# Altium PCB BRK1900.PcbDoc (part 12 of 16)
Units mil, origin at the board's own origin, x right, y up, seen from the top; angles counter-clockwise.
Board outline 8858.27 x 5905.51 mil, 10 copper layers (L1-TOP, L2-GND, L3-PWR, L4-GND, L5-PWR, L6-PWR, L7-GND, L8-SIG, L9-GND, L10-BOT), stack 48.824 mil thick; 456 components, 571 nets, 2296 pads, 2416 vias.
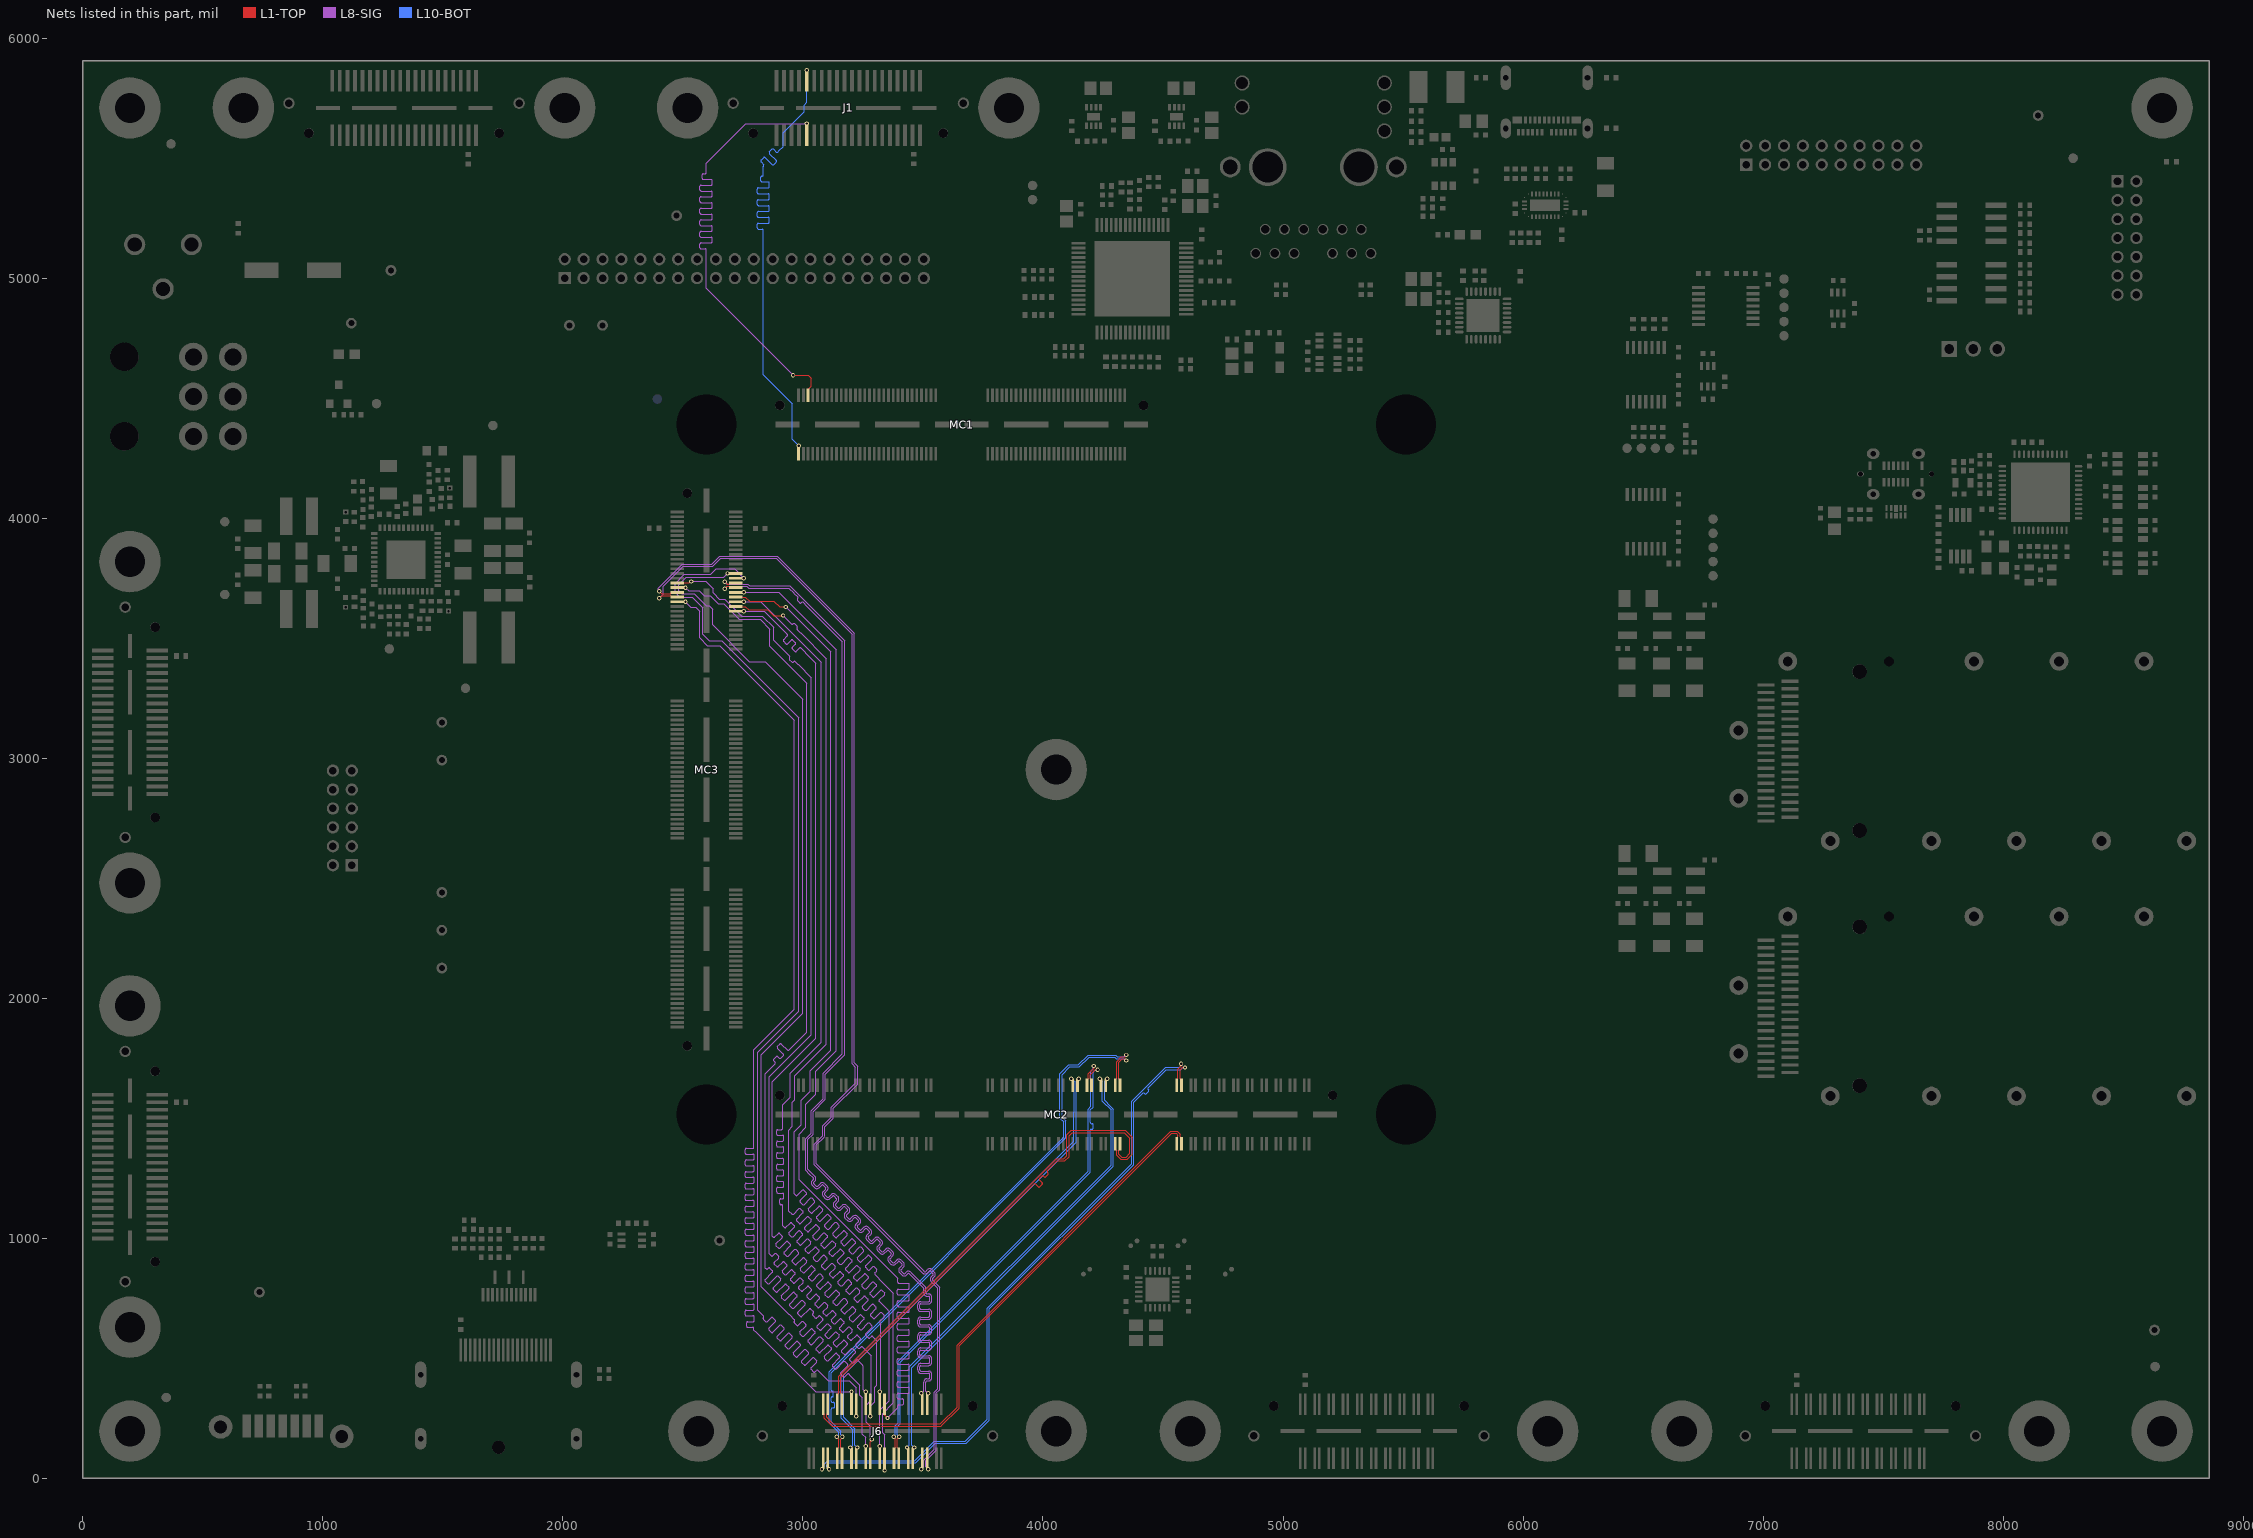
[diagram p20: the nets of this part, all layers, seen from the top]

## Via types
v1: diameter 18, hole 10, L1-TOP to L10-BOT, tented both sides, 2170 vias
v2: diameter 20, hole 10, L1-TOP to L10-BOT, tented both sides, 246 vias

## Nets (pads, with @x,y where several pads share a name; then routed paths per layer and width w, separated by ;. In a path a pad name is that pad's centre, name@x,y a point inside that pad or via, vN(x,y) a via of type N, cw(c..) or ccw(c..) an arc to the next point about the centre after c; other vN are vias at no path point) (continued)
SZG_PORTD_S26: J1.31 MC1.2 | length 2214
  L10-BOT w4.55: 2830.04,5424.99 ccw(c2830.04,5420.08) 2825.13,5420.08 2825.13,5405.35 ccw(c2830.04,5405.35) 2830.04,5400.44 2855.09,5400.44 cw(c2855.09,5395.53) 2860,5395.53 2860,5380.8 cw(c2855.09,5380.8) 2855.09,5375.89 2814.91,5375.89 ccw(c2814.91,5370.98) 2810,5370.98 2810,5356.25 ccw(c2814.91,5356.25) 2814.91,5351.34 2855.09,5351.34 cw(c2855.09,5346.43) 2860,5346.43 2860,5331.7 cw(c2855.09,5331.7) 2855.09,5326.79 2814.91,5326.79 ccw(c2814.91,5321.88) 2810,5321.88 2810,5307.15 ccw(c2814.91,5307.15) 2814.91,5302.24 2855.09,5302.24 cw(c2855.09,5297.33) 2860,5297.33 2860,5282.6 cw(c2855.09,5282.6) 2855.09,5277.69 2814.91,5277.69 ccw(c2814.91,5272.78) 2810,5272.78 2810,5258.05 ccw(c2814.91,5258.05) 2814.91,5253.14 2855.09,5253.14 cw(c2855.09,5248.23) 2860,5248.23 2860,5233.5 cw(c2855.09,5233.5) 2855.09,5228.59 2814.91,5228.59 ccw(c2814.91,5223.68) 2810,5223.68 2810,5208.95 ccw(c2814.91,5208.95) 2814.91,5204.04 2830.09,5204.04 cw(c2830.09,5199.13) 2835,5199.13 2835,5196.85 2835,4597 2956,4476 2956,4328.39 v1(2982.28,4302.11) ; 2830.09,5424.99 ccw(c2830.09,5429.9) 2835,5429.9 2835,5448.82 2835,5464.21 2835,5464.92 2836.25,5466.18 ccw(c2832.78,5469.65) 2836.25,5473.12 2825.52,5483.85 cw(c2828.99,5487.33) 2825.52,5490.8 2835.94,5501.21 cw(c2839.41,5497.74) 2842.88,5501.21 2871.29,5472.8 ccw(c2874.76,5476.27) 2878.24,5472.8 2888.65,5483.22 ccw(c2885.18,5486.69) 2888.65,5490.16 2860.24,5518.57 cw(c2863.71,5522.04) 2860.24,5525.52 2870.66,5535.93 cw(c2874.13,5532.46) 2877.6,5535.93 2888.33,5525.2 ccw(c2891.8,5528.67) 2895.28,5525.2 2901.57,5531.5 2917.32,5547.24 2917.32,5606.3 3004.63,5693.61 3004.63,5720.36 3015.78,5731.51 v1@3015.78,5869.46
  other v1: 3015.79,5866.17
SZG_PORTD_S27: J1.32 MC1.5 | length 2265.5
  L1-TOP w4.55: v1(2959,4595) 3022.86,4595 3034.34,4583.52 3034.34,4549.34 3021.65,4536.65 MC1.5@3021.65,4511.42
  L8-SIG w4.05: v1(2959,4595) 2597,4957 2597,5115.41 2597,5117.44 ccw(c2592.19,5117.44) 2592.19,5122.25 2575.88,5122.25 cw(c2575.88,5127.06) 2571.07,5127.06 2571.07,5141.49 cw(c2575.88,5141.49) 2575.88,5146.3 2617.19,5146.3 ccw(c2617.19,5151.11) 2622,5151.11 2622,5165.54 ccw(c2617.19,5165.54) 2617.19,5170.35 2575.88,5170.35 cw(c2575.88,5175.16) 2571.07,5175.16 2571.07,5189.59 cw(c2575.88,5189.59) 2575.88,5194.4 2617.19,5194.4 ccw(c2617.19,5199.21) 2622,5199.21 2622,5213.64 ccw(c2617.19,5213.64) 2617.19,5218.45 2575.88,5218.45 cw(c2575.88,5223.26) 2571.07,5223.26 2571.07,5237.69 cw(c2575.88,5237.69) 2575.88,5242.5 2617.19,5242.5 ccw(c2617.19,5247.31) 2622,5247.31 2622,5261.74 ccw(c2617.19,5261.74) 2617.19,5266.55 2575.88,5266.55 cw(c2575.88,5271.36) 2571.07,5271.36 2571.07,5285.79 cw(c2575.88,5285.79) 2575.88,5290.6 2617.19,5290.6 ccw(c2617.19,5295.41) 2622,5295.41 2622,5309.84 ccw(c2617.19,5309.84) 2617.19,5314.65 2575.88,5314.65 cw(c2575.88,5319.46) 2571.07,5319.46 2571.07,5333.89 cw(c2575.88,5333.89) 2575.88,5338.7 2617.19,5338.7 ccw(c2617.19,5343.51) 2622,5343.51 2622,5357.94 ccw(c2617.19,5357.94) 2617.19,5362.75 2575.88,5362.75 cw(c2575.88,5367.56) 2571.07,5367.56 2571.07,5381.99 cw(c2575.88,5381.99) 2575.88,5386.8 2617.19,5386.8 ccw(c2617.19,5391.61) 2622,5391.61 2622,5406.04 ccw(c2617.19,5406.04) 2617.19,5410.85 2584.93,5410.85 cw(c2584.93,5415.66) 2580.12,5415.66 2580.12,5430.09 cw(c2584.93,5430.09) 2584.93,5434.9 2592.19,5434.9 ccw(c2592.19,5439.71) 2597,5439.71 2597,5464.57 2597,5478.89 2761.97,5643.86 v1(3015.78,5643.86)
SZG_PORTE_C2P_CLKN: J6.36 MC3.150 | length 4941.1
  L1-TOP w3.3: v1@2675.08,3734.25 2676.08,3734.25 2685.36,3724.97 2692.1,3724.97 2697.44,3730.32 MC3.150@2720.08,3730.32
  L8-SIG w3.15: v1@2675.08,3734.25 2684.36,3724.97 2770.76,3724.97 2777.99,3717.74 2944.99,3717.74 3173.87,3488.86 3173.87,1764.49 3093.64,1684.26 3093.64,1578.64 3043,1528 3043,1434.07 3020.95,1412.02 3020.95,1287.05 3031.65,1276.36 3049.97,1258.04 cw(c3040.33,1248.4) 3049.97,1238.76 3045.22,1234.01 ccw(c3048.49,1230.74) 3045.22,1227.46 3055.04,1217.64 ccw(c3058.31,1220.92) 3061.58,1217.64 3071.63,1227.69 cw(c3081.27,1218.05) 3090.91,1227.69 3100.73,1217.87 cw(c3091.09,1208.23) 3102.05,1200.12 3102.05,1199.91 3090.67,1188.53 ccw(c3093.94,1185.26) 3090.67,1181.98 3100.49,1172.16 ccw(c3103.76,1175.43) 3107.04,1172.16 ; 3107.06,1172.18 3117.1,1182.22 cw(c3126.74,1172.58) 3136.37,1182.22 3146.19,1172.4 cw(c3136.56,1162.76) 3147.51,1154.65 3147.51,1154.44 3136.13,1143.06 ccw(c3139.41,1139.79) 3136.13,1136.51 3145.96,1126.69 ccw(c3149.23,1129.97) 3152.5,1126.69 3162.56,1136.75 cw(c3172.2,1127.12) 3181.84,1136.75 3191.66,1126.93 cw(c3182.02,1117.29) 3192.98,1109.19 3192.98,1108.97 3181.6,1097.6 ccw(c3184.87,1094.32) 3181.6,1091.05 3191.42,1081.23 ccw(c3194.7,1084.5) 3197.97,1081.23 ; 3197.99,1081.25 3208.03,1091.29 cw(c3217.67,1081.65) 3227.31,1091.29 3237.13,1081.46 cw(c3227.49,1071.83) 3238.45,1063.72 3238.45,1063.51 3227.07,1052.13 ccw(c3230.34,1048.85) 3227.07,1045.58 3236.89,1035.76 ccw(c3240.16,1039.03) 3243.44,1035.76 ; 3243.46,1035.78 3253.5,1045.82 cw(c3263.14,1036.18) 3272.77,1045.82 3282.6,1036 cw(c3272.96,1026.36) 3283.91,1018.25 3283.91,1018.04 3272.53,1006.66 ccw(c3275.81,1003.39) 3272.53,1000.11 3282.36,990.29 ccw(c3285.63,993.57) 3288.9,990.29 3298.96,1000.35 cw(c3308.6,990.72) 3318.24,1000.35 3328.06,990.53 cw(c3318.42,980.89) 3329.38,972.79 3329.38,972.57 3318,961.2 ccw(c3321.27,957.92) 3318,954.65 3327.82,944.83 ccw(c3331.1,948.1) 3334.37,944.83 ; 3334.39,944.85 3344.43,954.89 cw(c3354.07,945.25) 3363.71,954.89 3373.53,945.06 cw(c3363.89,935.43) 3374.85,927.32 3374.85,927.11 3363.47,915.73 ccw(c3366.74,912.45) 3363.47,909.18 3373.29,899.36 ccw(c3376.56,902.63) 3379.84,899.36 ; 3379.86,899.38 3389.9,909.42 cw(c3399.54,899.78) 3409.17,909.42 3419,899.6 cw(c3409.36,889.96) 3420.31,881.85 3420.31,881.64 3408.93,870.26 ccw(c3412.21,866.99) 3408.93,863.71 3418.76,853.89 ccw(c3422.03,857.17) 3425.3,853.89 ; 3425.33,853.91 3430.07,858.66 cw(c3439.71,849.02) 3449.35,858.66 3453.64,854.36 3511.93,796.07 3511.93,779.4 3511.93,773.33 ccw(c3516.56,773.33) 3516.56,768.7 3523.3,768.7 cw(c3523.3,755.07) 3536.93,755.07 3536.93,741.17 cw(c3523.3,741.17) 3523.3,727.54 3491.56,727.54 ccw(c3491.56,722.91) 3486.93,722.91 3486.93,709.03 ccw(c3491.56,709.03) 3491.56,704.39 3523.3,704.39 cw(c3523.3,690.76) 3536.93,690.76 3536.93,676.87 cw(c3523.3,676.87) 3523.3,663.24 3491.56,663.25 ccw(c3491.56,658.62) 3486.93,658.62 3486.93,644.72 ccw(c3491.56,644.72) 3491.56,640.09 3523.3,640.09 cw(c3523.3,626.46) 3536.93,626.46 3536.93,612.58 cw(c3523.3,612.58) 3523.3,598.95 3491.56,598.95 ccw(c3491.56,594.32) 3486.93,594.32 3486.93,580.42 ccw(c3491.56,580.42) 3491.56,575.79 3523.3,575.79 cw(c3523.3,562.16) 3536.93,562.16 3536.93,548.28 cw(c3523.3,548.28) 3523.3,534.64 3491.56,534.64 ccw(c3491.56,530.01) 3486.93,530.01 3486.93,516.12 ccw(c3491.56,516.12) 3491.56,511.49 3523.3,511.5 cw(c3523.3,497.87) 3536.93,497.87 3536.93,483.97 cw(c3523.3,483.97) 3523.3,470.34 3491.56,470.34 ccw(c3491.56,465.71) 3486.93,465.71 3486.93,451.83 ccw(c3491.56,451.83) 3491.56,447.2 3523.3,447.2 cw(c3523.3,433.57) 3536.93,433.57 3536.93,419.67 cw(c3523.3,419.67) 3523.3,406.04 3516.56,406.04 ccw(c3516.56,401.41) 3511.93,401.41 3511.93,374.02 3511.93,364.12 v1@3521.21,354.84
  other v1: 3522.31,354.84 2675.08,3735.25
SZG_PORTE_C2P_CLKP: J6.34 MC3.148 | length 4941
  L1-TOP w3.3: v1@2675.08,3706.69 2676.18,3706.69 2685.46,3715.97 2692.1,3715.97 2697.44,3710.63 MC3.148@2720.08,3710.63
  L8-SIG w3.15: v1@2675.08,3706.69 2684.36,3715.97 2767.03,3715.97 2774.26,3708.74 2941.26,3708.74 2960.83,3689.17 2961.94,3688.06 2978.31,3671.69 cw(c2975.04,3668.42) 2978.31,3665.14 2976.83,3663.66 ccw(c2980.1,3660.38) 2976.83,3657.11 2986.65,3647.29 ccw(c2989.92,3650.56) 2993.2,3647.29 2994.68,3648.77 cw(c2997.95,3645.5) 3001.23,3648.77 3014.83,3635.17 3015.95,3634.05 3164.87,3485.13 3164.87,1768.22 3084.64,1687.99 3084.64,1582.36 3034,1531.73 3034,1437.79 3011.95,1415.74 3011.95,1283.33 3025.28,1269.99 3043.6,1251.67 cw(c3040.33,1248.4) 3043.6,1245.13 3038.85,1240.38 ccw(c3048.49,1230.74) 3038.88,1221.07 3048.64,1211.31 ccw(c3058.31,1220.92) 3067.95,1211.28 3077.99,1221.32 cw(c3081.27,1218.05) 3084.54,1221.32 3094.36,1211.5 cw(c3091.09,1208.23) 3094.36,1204.95 3084.3,1194.89 ccw(c3093.94,1185.26) 3084.33,1175.59 3094.1,1165.82 ccw(c3103.76,1175.43) 3111.87,1164.48 3112.08,1164.48 3123.46,1175.86 cw(c3126.74,1172.58) 3130.01,1175.86 3139.83,1166.03 cw(c3136.56,1162.76) 3139.83,1159.49 ; 3139.81,1159.46 3129.77,1149.43 ccw(c3139.41,1139.79) 3129.8,1130.12 3139.56,1120.36 ccw(c3149.23,1129.97) 3157.34,1119.01 3157.55,1119.01 3168.93,1130.39 cw(c3172.2,1127.12) 3175.48,1130.39 3185.3,1120.57 cw(c3182.02,1117.29) 3185.3,1114.02 ; 3185.27,1114 3175.24,1103.96 ccw(c3184.87,1094.32) 3175.27,1084.66 3185.03,1074.89 ccw(c3194.7,1084.5) 3202.8,1073.54 3203.02,1073.54 3214.39,1084.92 cw(c3217.67,1081.65) 3220.94,1084.92 3230.76,1075.1 cw(c3227.49,1071.83) 3230.76,1068.55 3220.7,1058.49 ccw(c3230.34,1048.85) 3220.73,1039.19 3230.5,1029.42 ccw(c3240.16,1039.03) 3248.27,1028.08 3248.48,1028.08 3259.86,1039.46 cw(c3263.14,1036.18) 3266.41,1039.46 3276.23,1029.63 cw(c3272.96,1026.36) 3276.23,1023.09 ; 3276.21,1023.06 3266.17,1013.03 ccw(c3275.81,1003.39) 3266.2,993.72 3275.96,983.96 ccw(c3285.63,993.57) 3293.74,982.61 3293.95,982.61 3305.33,993.99 cw(c3308.6,990.72) 3311.88,993.99 3321.7,984.17 cw(c3318.42,980.89) 3321.7,977.62 ; 3321.68,977.6 3311.64,967.56 ccw(c3321.27,957.92) 3311.67,948.25 3321.43,938.49 ccw(c3331.1,948.1) 3339.2,937.14 3339.42,937.14 3350.8,948.52 cw(c3354.07,945.25) 3357.34,948.52 3367.16,938.7 cw(c3363.89,935.43) 3367.16,932.15 3357.1,922.09 ccw(c3366.74,912.45) 3357.13,902.79 3366.9,893.02 ccw(c3376.56,902.63) 3384.67,891.68 3384.88,891.68 3396.26,903.06 cw(c3399.54,899.78) 3402.81,903.06 3412.63,893.23 cw(c3409.36,889.96) 3412.63,886.69 ; 3412.61,886.66 3402.57,876.63 ccw(c3412.21,866.99) 3402.6,857.32 3412.36,847.56 ccw(c3422.03,857.17) 3430.14,846.21 3430.35,846.21 3436.43,852.29 cw(c3439.71,849.02) 3442.98,852.29 3447.28,848 3502.93,792.35 3502.93,779.4 3502.93,773.33 ccw(c3516.56,773.33) 3516.56,759.7 3523.3,759.7 cw(c3523.3,755.07) 3527.93,755.07 3527.93,741.17 cw(c3523.3,741.17) 3523.3,736.54 3491.56,736.54 ccw(c3491.56,722.91) 3477.93,722.91 3477.93,709.03 ccw(c3491.56,709.03) 3491.56,695.39 3523.3,695.39 cw(c3523.3,690.76) 3527.93,690.76 3527.93,676.87 cw(c3523.3,676.87) 3523.3,672.24 3491.56,672.25 ccw(c3491.56,658.62) 3477.93,658.62 3477.93,644.72 ccw(c3491.56,644.72) 3491.56,631.09 3523.3,631.09 cw(c3523.3,626.46) 3527.93,626.46 3527.93,612.58 cw(c3523.3,612.58) 3523.3,607.95 3491.56,607.95 ccw(c3491.56,594.32) 3477.93,594.32 3477.93,580.42 ccw(c3491.56,580.42) 3491.56,566.79 3523.3,566.79 cw(c3523.3,562.16) 3527.93,562.16 3527.93,548.28 cw(c3523.3,548.28) 3523.3,543.64 3491.56,543.64 ccw(c3491.56,530.01) 3477.93,530.01 3477.93,516.12 ccw(c3491.56,516.12) 3491.56,502.49 3523.3,502.5 cw(c3523.3,497.87) 3527.93,497.87 3527.93,483.97 cw(c3523.3,483.97) 3523.3,479.34 3491.56,479.34 ccw(c3491.56,465.71) 3477.93,465.71 3477.93,451.83 ccw(c3491.56,451.83) 3491.56,438.2 3523.3,438.2 cw(c3523.3,433.57) 3527.93,433.57 3527.93,419.67 cw(c3523.3,419.67) 3523.3,415.04 3516.56,415.04 ccw(c3516.56,401.41) 3502.93,401.41 3502.93,374.02 3502.93,364.12 v1@3493.65,354.84
  other v1: 3492.55,354.84 2675.08,3705.59
SZG_PORTE_P2C_CLKN: J6.35 MC3.145 | length 4940.7
  L1-TOP w3.3: v1@2401.77,3694.88 2411.05,3685.6 2448.88,3685.6 2454.22,3690.95 MC3.145@2476.77,3690.95
  L8-SIG w3.15: v1(2401.77,3695.88) 2401.77,3699.9 2397.91,3703.76 2397.91,3708.63 2497.21,3807.94 2619.94,3807.94 2654,3842 2892.73,3842 3213.72,3521 3213.72,1731.59 3227.84,1717.47 3227.84,1642.84 3127,1542 3127,1500.1 3091.64,1464.73 3091.64,1424.64 3089,1422 3056.24,1389.24 3056.24,1310.82 3500.82,866.24 3505.11,861.94 ccw(c3508.39,865.22) 3511.66,861.94 3518.95,869.23 cw(c3528.59,859.59) 3538.22,869.23 3548.05,859.41 cw(c3538.41,849.77) 3548.05,840.13 3540.76,832.85 ccw(c3544.03,829.57) 3540.76,826.3 3563.45,803.61 3570,797.06 3570,369.93 3556,355.93 3556,117.07 3511.93,73 3511.93,48.14 v1@3521.21,38.86
  other v1: 3522.31,38.86
SZG_PORTE_P2C_CLKP: J6.33 MC3.143 | length 4939.9
  L1-TOP w3.3: v1@2401.77,3667.32 2411.05,3676.6 2448.69,3676.6 2454.03,3671.26 MC3.143@2476.77,3671.26
  L8-SIG w3.15: v1@2401.77,3667.32 2417.46,3683.01 2417.46,3715.46 2500.94,3798.94 2623.67,3798.94 2657.73,3833 2889,3833 3204.72,3517.28 3204.72,1727.86 3218.84,1713.74 3218.84,1646.57 3118,1545.73 3118,1503.83 3082.64,1468.46 3082.64,1428.36 3047.24,1392.97 3047.24,1307.09 3494.45,859.88 3498.72,855.61 ccw(c3508.39,865.22) 3518.03,855.58 3525.31,862.87 cw(c3528.59,859.59) 3531.86,862.87 3541.68,853.05 cw(c3538.41,849.77) 3541.68,846.5 3534.4,839.21 ccw(c3544.03,829.57) 3534.42,819.91 3557.09,797.24 3561,793.33 3561,373.66 3547,359.66 3547,120.8 3502.93,76.73 3502.93,48.14 v1@3493.65,38.86
  other v1: 3492.55,38.86 2401.77,3666.22
SZG_PORTE_REFCLKN: J6.15 MC2.67 | length 1966.5
  L10-BOT w3.3: v1(3227.03,128.86) 3216.65,139.24 3216.65,206.46 3169.29,253.82 3169.29,432.15 4137.89,1400.76 4137.89,1522.23 4138.36,1522.7 4138.36,1654.15 v1(4149.61,1665.4)
SZG_PORTE_REFCLKP: J6.13 MC2.65 | length 1966.5
  L10-BOT w3.3: v1(3197.28,128.86) 3207.65,139.24 3207.65,202.73 3160.29,250.09 3160.29,435.88 4128.89,1404.48 4128.89,1525.96 4129.36,1526.42 4129.36,1654.15 v1(4118.11,1665.4)
SZG_PORTE_RX0N: J6.7 MC2.83 | length 2732.1
  L1-TOP w3.3: MC2.83@4576.77,1637.4 4576.77,1660.04 4571.43,1665.38 4571.43,1701.35 4585.25,1715.17 4588.83,1711.59 v1(4591.56,1711.59)
  L10-BOT w3.3: v1(3108.92,38.86) 3098.54,49.24 3098.54,55.12 3107.91,64.48 3469.22,64.48 3550.74,146 3680.73,146 3774.08,239.35 3776.72,241.99 3776.72,705.85 4377.95,1307.09 4377.95,1566.93 4397.51,1586.48 4415.15,1604.12 cw(c4418.44,1600.83) 4421.74,1604.12 4423.25,1602.61 ccw(c4426.54,1605.91) 4429.84,1602.61 4439.72,1612.5 ccw(c4436.43,1615.79) 4439.72,1619.09 4438.21,1620.6 cw(c4441.51,1623.89) 4438.21,1627.19 4454.19,1643.16 4514.25,1703.23 4573.31,1703.23 4580.05,1709.97 4589.95,1709.97 v1(4591.56,1711.59)
SZG_PORTE_RX0P: J6.5 MC2.81 | length 2732.1
  L1-TOP w3.3: MC2.81@4557.09,1637.4 4557.09,1660.04 4562.43,1665.38 4562.43,1705.08 4578.88,1721.53 4575.3,1725.12 v1(4575.3,1727.85)
  L10-BOT w3.3: v1(3079.17,38.86) 3089.54,49.24 3089.54,58.85 3104.18,73.48 3465.49,73.48 3547.01,155 3677,155 3767.72,245.72 3767.72,709.58 4368.95,1310.81 4368.95,1570.66 4510.53,1712.23 4569.58,1712.23 4573.69,1716.34 4573.69,1726.24 v1(4575.3,1727.85)
SZG_PORTE_RX1N: J6.11 MC2.79 | length 2505.9
  L1-TOP w3.3: J6.11@3162.94,83.86 3162.94,123.03 3157.6,128.37 3157.6,163.95 3164.6,170.95 v1(3164.6,173.23) ; MC2.79@4320.87,1637.4 4320.87,1660.04 4315.52,1665.38 4315.52,1732.85 4330.71,1748.03 4342.52,1748.03 4346.46,1744.09 v1(4346.46,1741.03)
  L10-BOT w3.3: v1(3164.6,173.23) 3164.6,175.51 3157.6,182.51 3157.6,196.27 3118.11,235.76 3118.11,263.78 3118.11,288.73 cw(c3122.77,288.73) 3122.77,293.39 3127.04,293.39 ccw(c3127.04,298.05) 3131.7,298.05 3131.7,312.03 ccw(c3127.04,312.03) 3127.04,316.69 3122.77,316.69 cw(c3122.77,321.35) 3118.11,321.35 3118.11,335.33 cw(c3122.77,335.33) 3122.77,339.99 ccw(c3122.77,344.65) 3127.43,344.65 3127.43,358.63 ccw(c3122.77,358.63) 3122.77,363.29 cw(c3122.77,367.95) 3118.11,367.95 3118.11,401.57 3118.11,440.94 4095.61,1418.45 4095.61,1489.26 4079.83,1505.05 4079.83,1682.19 4111.64,1714.01 4151.01,1714.01 4191.79,1754.78 4298.58,1754.78 4305.33,1748.03 4337.17,1748.03 4344.17,1741.03 v1(4346.46,1741.03)
SZG_PORTE_RX1P: J6.9 MC2.77 | length 2505.9
  L1-TOP w3.3: v1(3141.6,173.23) 3141.6,170.95 3148.6,163.95 3148.6,128.37 3143.26,123.03 J6.9@3143.26,83.86 ; MC2.77@4301.18,1637.4 4301.18,1660.04 4306.52,1665.38 4306.52,1736.57 4326.98,1757.03 4342.52,1757.03 4346.46,1760.97 v1(4346.46,1764.03)
  L10-BOT w3.3: v1(3141.6,173.23) 3141.6,175.51 3148.6,182.51 3148.6,192.54 3109.11,232.03 3109.11,401.57 3109.11,444.67 4086.61,1422.18 4086.61,1485.53 4070.83,1501.32 4070.83,1685.92 4107.92,1723.01 4147.29,1723.01 4188.06,1763.78 4302.31,1763.78 4309.06,1757.03 4337.17,1757.03 4344.17,1764.03 v1(4346.46,1764.03)
SZG_PORTE_RX2N: J6.31 MC2.75 | length 1908.2
  L10-BOT w3.3: v1(3463.26,128.86) 3452.88,139.24 3452.88,460.75 4292.46,1300.34 4292.46,1538.54 4278.02,1552.98 4256.47,1574.53 4256.47,1654.15 v1(4267.72,1665.4)
SZG_PORTE_RX2P: J6.29 MC2.73 | length 1908.2
  L10-BOT w3.3: v1(3433.5,128.86) 3443.88,139.24 3443.88,464.48 4283.46,1304.07 4283.46,1534.81 4247.47,1570.8 4247.47,1654.15 v1(4236.22,1665.4)
SZG_PORTE_RX3N: J6.27 MC2.71 | length 2079.1
  L1-TOP w3.3: J6.27@3399.16,83.86 3399.16,123.03 3393.82,128.37 3393.82,165.17 3400.82,172.17 v1(3400.82,173.23) ; MC2.71@4202.76,1637.4 4202.76,1660.04 4197.41,1665.38 4197.41,1681.67 4220.47,1704.72 4223.45,1701.74 v1(4227.39,1701.74)
  L10-BOT w3.3: v1(3400.82,173.23) 3400.82,175.51 3393.82,182.51 3393.82,185.96 3393.82,215.2 3406,227.39 3406,484.63 4197.41,1276.04 4197.41,1425.2 4197.41,1450.15 cw(c4202.07,1450.15) 4202.07,1454.81 4204.21,1454.81 ccw(c4204.21,1459.47) 4208.87,1459.47 4208.87,1473.45 ccw(c4204.21,1473.45) 4204.21,1478.11 4202.07,1478.11 cw(c4202.07,1482.77) 4197.41,1482.77 4197.41,1500 4197.41,1535.08 4208.66,1546.33 4208.66,1692.91 4215.88,1700.13 4225.78,1700.13 v1(4227.39,1701.74)
SZG_PORTE_RX3P: J6.25 MC2.69 | length 2079.1
  L1-TOP w3.3: v1(3377.82,173.23) 3377.82,172.17 3384.82,165.17 3384.82,128.37 3379.48,123.03 J6.25@3379.48,83.86 ; MC2.69@4183.07,1637.4 4183.07,1660.04 4188.41,1665.38 4188.41,1685.39 4214.11,1711.09 4211.13,1714.07 v1(4211.13,1718.01)
  L10-BOT w3.3: v1(3377.82,173.23) 3377.82,175.51 3384.82,182.51 3384.82,189.68 3384.82,218.93 3397,231.12 3397,488.35 4188.41,1279.76 4188.41,1538.81 4199.66,1550.05 4199.66,1696.64 4209.51,1706.49 4209.51,1716.39 v1(4211.13,1718.01)
SZG_PORTE_S0: J6.14 MC3.141 | length 4899.6
  L8-SIG w4.05: v1(2510.77,3651.58) 2533.46,3628.88 2552.83,3628.88 2569.47,3612.25 2569.47,3501.4 2602.36,3468.5 2653.5,3468.5 2964.38,3157.62 2964.38,1954.01 2796,1785.62 2796,1405.51 2796,1379.44 cw(c2791.19,1379.44) 2791.19,1374.63 2764.15,1374.63 ccw(c2764.15,1369.82) 2759.34,1369.82 2759.34,1355.39 ccw(c2764.15,1355.39) 2764.15,1350.58 2792.04,1350.58 cw(c2792.04,1345.77) 2796.85,1345.77 2796.85,1331.34 cw(c2792.04,1331.34) 2792.04,1326.53 2764.15,1326.53 ccw(c2764.15,1321.72) 2759.34,1321.72 2759.34,1307.29 ccw(c2764.15,1307.29) 2764.15,1302.48 2792.04,1302.48 cw(c2792.04,1297.67) 2796.85,1297.67 2796.85,1283.24 cw(c2792.04,1283.24) 2792.04,1278.43 2764.15,1278.43 ccw(c2764.15,1273.62) 2759.34,1273.62 2759.34,1259.19 ccw(c2764.15,1259.19) 2764.15,1254.38 2792.04,1254.38 cw(c2792.04,1249.57) 2796.85,1249.57 2796.85,1235.14 cw(c2792.04,1235.14) 2792.04,1230.33 2764.15,1230.33 ccw(c2764.15,1225.52) 2759.34,1225.52 2759.34,1211.09 ccw(c2764.15,1211.09) 2764.15,1206.28 2792.04,1206.28 cw(c2792.04,1201.47) 2796.85,1201.47 2796.85,1187.04 cw(c2792.04,1187.04) 2792.04,1182.23 2764.15,1182.23 ccw(c2764.15,1177.42) 2759.34,1177.42 2759.34,1162.99 ccw(c2764.15,1162.99) 2764.15,1158.18 2792.04,1158.18 cw(c2792.04,1153.37) 2796.85,1153.37 2796.85,1138.94 cw(c2792.04,1138.94) 2792.04,1134.13 2764.15,1134.13 ccw(c2764.15,1129.32) 2759.34,1129.32 2759.34,1114.89 ccw(c2764.15,1114.89) 2764.15,1110.08 2792.04,1110.08 cw(c2792.04,1105.27) 2796.85,1105.27 2796.85,1090.84 cw(c2792.04,1090.84) 2792.04,1086.03 2764.15,1086.03 ccw(c2764.15,1081.22) 2759.34,1081.22 2759.34,1066.79 ccw(c2764.15,1066.79) 2764.15,1061.98 2792.04,1061.98 cw(c2792.04,1057.17) 2796.85,1057.17 2796.85,1042.74 cw(c2792.04,1042.74) 2792.04,1037.93 2764.15,1037.93 ccw(c2764.15,1033.12) 2759.34,1033.12 2759.34,1018.69 ccw(c2764.15,1018.69) 2764.15,1013.88 2792.04,1013.88 cw(c2792.04,1009.07) 2796.85,1009.07 2796.85,994.64 cw(c2792.04,994.64) 2792.04,989.83 2764.15,989.83 ccw(c2764.15,985.02) 2759.34,985.02 2759.34,970.59 ccw(c2764.15,970.59) 2764.15,965.78 2792.04,965.78 cw(c2792.04,960.97) 2796.85,960.97 2796.85,946.54 cw(c2792.04,946.54) 2792.04,941.73 2764.15,941.73 ccw(c2764.15,936.92) 2759.34,936.92 2759.34,922.49 ccw(c2764.15,922.49) 2764.15,917.68 2792.04,917.68 cw(c2792.04,912.87) 2796.85,912.87 2796.85,898.44 cw(c2792.04,898.44) 2792.04,893.63 2764.15,893.63 ccw(c2764.15,888.82) 2759.34,888.82 2759.34,874.39 ccw(c2764.15,874.39) 2764.15,869.58 2792.04,869.58 cw(c2792.04,864.77) 2796.85,864.77 2796.85,850.34 cw(c2792.04,850.34) 2792.04,845.53 2764.15,845.53 ccw(c2764.15,840.72) 2759.34,840.72 2759.34,826.29 ccw(c2764.15,826.29) 2764.15,821.48 2792.04,821.48 cw(c2792.04,816.67) 2796.85,816.67 2796.85,802.24 cw(c2792.04,802.24) 2792.04,797.43 2764.15,797.43 ccw(c2764.15,792.62) 2759.34,792.62 2759.34,778.19 ccw(c2764.15,778.19) 2764.15,773.38 2792.04,773.38 cw(c2792.04,768.57) 2796.85,768.57 2796.85,754.14 cw(c2792.04,754.14) 2792.04,749.33 2764.15,749.33 ccw(c2764.15,744.52) 2759.34,744.52 2759.34,730.09 ccw(c2764.15,730.09) 2764.15,725.28 2792.04,725.28 cw(c2792.04,720.47) 2796.85,720.47 2796.85,706.04 cw(c2792.04,706.04) 2792.04,701.23 2764.15,701.23 ccw(c2764.15,696.42) 2759.34,696.42 2759.34,681.99 ccw(c2764.15,681.99) 2764.15,677.18 2792.04,677.18 cw(c2792.04,672.37) 2796.85,672.37 2796.85,657.94 cw(c2792.04,657.94) 2792.04,653.13 2770.5,653.13 ccw(c2770.5,648.32) 2765.69,648.32 2765.69,633.89 ccw(c2770.5,633.89) 2770.5,629.08 2791.19,629.08 cw(c2791.19,624.27) 2796,624.27 2796,617.39 2803.15,610.24 3052.54,360.84 v1(3202.31,360.84)
SZG_PORTE_S1: J6.16 MC3.152 | length 4902.2
  L8-SIG w4.05: v1(2754.08,3750) 2715.08,3789 2639.39,3789 2616.89,3766.5 2506.5,3766.5 2467.38,3727.38 2467.38,3691.64 2487.77,3671.26 2538.79,3671.26 2583.23,3626.83 2583.23,3516.77 2610,3490 2661,3490 2982.38,3168.62 2982.38,1945.01 2812,1774.62 2812,700.55 2817.09,695.45 2818.52,694.02 2835.17,677.37 cw(c2831.77,673.97) 2835.17,670.57 ccw(c2838.57,667.17) 2835.17,663.77 2845.37,653.57 ccw(c2848.77,656.97) 2852.18,653.57 2867.94,669.33 cw(c2871.34,665.93) 2874.74,669.33 2884.95,659.13 cw(c2881.55,655.73) 2884.95,652.32 2858.31,625.68 ccw(c2861.71,622.28) 2858.31,618.88 2868.51,608.68 ccw(c2871.91,612.08) 2875.31,608.68 2903.87,637.23 cw(c2907.27,633.83) 2910.67,637.23 2920.87,627.03 cw(c2917.47,623.63) 2920.87,620.23 2892.32,591.67 ccw(c2895.72,588.27) 2892.32,584.87 2902.52,574.67 ccw(c2905.92,578.07) 2909.33,574.67 2937.88,603.22 cw(c2941.28,599.82) 2944.68,603.22 2954.88,593.02 cw(c2951.48,589.62) 2954.88,586.21 2926.33,557.66 ccw(c2929.73,554.26) 2926.33,550.86 2936.53,540.66 ccw(c2939.94,544.06) 2943.34,540.66 2971.89,569.21 cw(c2975.29,565.81) 2978.69,569.21 2988.9,559.01 cw(c2985.49,555.6) 2988.9,552.2 2960.34,523.65 ccw(c2963.74,520.25) 2960.34,516.85 2970.55,506.64 ccw(c2973.95,510.04) 2977.35,506.64 3005.9,535.2 cw(c3009.3,531.8) 3012.7,535.2 3022.91,524.99 cw(c3019.51,521.59) 3022.91,518.19 2994.35,489.64 ccw(c2997.76,486.24) 2994.35,482.84 3004.56,472.63 ccw(c3007.96,476.03) 3011.36,472.63 3039.91,501.18 cw(c3043.31,497.78) 3046.72,501.18 3056.92,490.98 cw(c3053.52,487.58) 3056.92,484.18 3033.86,461.12 ccw(c3037.26,457.72) 3033.86,454.31 3044.06,444.11 ccw(c3047.46,447.51) 3050.86,444.11 3056.25,449.5 cw(c3059.65,446.09) 3063.05,449.5 3064.48,448.06 3106.42,406.12 3194.03,406.12 3222,378.16 v1(3222,258.84)
SZG_PORTE_S2: J6.17 MC3.154 | length 4902.2
  L8-SIG w4.05: v1(2686.08,3769.69) 2669.89,3753.5 2513.63,3753.5 2482.38,3722.25 2482.38,3698.64 2496.03,3685 2546.51,3685 2596.51,3635 2610,3635 2624,3621 2624,3555 2777.43,3401.57 2843.43,3401.57 2998.38,3246.62 2998.38,1937.01 2827,1765.62 2827,798.98 2941.24,684.74 2942.67,683.31 2964.23,661.75 cw(c2960.83,658.35) 2964.23,654.95 ccw(c2967.63,651.55) 2964.23,648.15 2974.43,637.94 ccw(c2977.84,641.34) 2981.24,637.94 2995.12,651.83 cw(c2998.52,648.43) 3001.92,651.83 3012.13,641.62 cw(c3008.73,638.22) 3012.13,634.82 2987.37,610.06 ccw(c2990.77,606.66) 2987.37,603.26 2997.57,593.06 ccw(c3000.97,596.46) 3004.37,593.06 3032.93,621.61 cw(c3036.33,618.21) 3039.73,621.61 3049.93,611.41 cw(c3046.53,608.01) 3049.93,604.6 3021.38,576.05 ccw(c3024.78,572.65) 3021.38,569.25 3031.58,559.05 ccw(c3034.99,562.45) 3038.39,559.05 3066.94,587.6 cw(c3070.34,584.2) 3073.74,587.6 3083.95,577.39 cw(c3080.54,573.99) 3083.95,570.59 3055.39,542.04 ccw(c3058.79,538.64) 3055.39,535.24 3065.6,525.03 ccw(c3069,528.43) 3072.4,525.03 3100.95,553.59 cw(c3104.35,550.19) 3107.75,553.59 3117.96,543.38 cw(c3114.56,539.98) 3117.96,536.58 3089.4,508.03 ccw(c3092.81,504.63) 3089.4,501.23 3099.61,491.02 ccw(c3103.01,494.42) 3106.41,491.02 3134.96,519.57 cw(c3138.36,516.17) 3141.77,519.57 3151.97,509.37 cw(c3148.57,505.97) 3151.97,502.57 3123.42,474.02 ccw(c3126.82,470.61) 3123.42,467.21 3133.62,457.01 ccw(c3137.02,460.41) 3140.42,457.01 3168.97,485.56 cw(c3172.38,482.16) 3175.78,485.56 3185.98,475.36 cw(c3182.58,471.96) 3185.98,468.56 3157.43,440 ccw(c3160.83,436.6) 3157.43,433.2 3167.63,423 ccw(c3171.03,426.4) 3174.43,423 3185.31,433.87 cw(c3188.71,430.47) 3192.11,433.87 3193.54,432.44 3237.81,388.18 3237.81,346.29 3247.68,336.42 3247.68,184.76 3261.37,171.07 v1(3261.37,134.86)
SZG_PORTE_S3: J6.18 MC3.147 | length 4901.1
  L8-SIG w4.05: v1(2510.77,3710.63) 2524.55,3696.85 2569.15,3696.85 2589,3677 2614,3677 2648,3643 2670,3643 2735,3578 2821.43,3578 2862.2,3537.22 2862.2,3466.14 3016.18,3312.16 3016.18,1858.87 2960.54,1803.24 2942.11,1784.8 cw(c2938.7,1788.2) 2935.3,1784.8 2910.6,1809.5 ccw(c2907.2,1806.1) 2903.8,1809.5 2893.6,1799.3 ccw(c2897,1795.89) 2893.6,1792.49 2918.39,1767.7 cw(c2914.98,1764.3) 2918.39,1760.9 2908.18,1750.7 cw(c2904.78,1754.1) 2901.38,1750.7 2895.54,1756.53 ccw(c2892.14,1753.13) 2888.74,1756.53 2878.54,1746.33 ccw(c2881.94,1742.93) 2878.54,1739.53 2884.28,1733.78 cw(c2880.88,1730.38) 2884.28,1726.98 2865.39,1708.08 2844,1686.69 2844,876.47 2845.6,874.87 2847.03,873.44 ccw(c2850.43,876.84) 2853.83,873.44 2856.12,875.73 cw(c2859.52,872.33) 2862.92,875.73 2873.13,865.53 cw(c2869.72,862.12) 2873.13,858.72 2842.74,828.34 ccw(c2846.14,824.94) 2842.74,821.54 2852.95,811.33 ccw(c2856.35,814.74) 2859.75,811.33 2890.13,841.72 ; 2890.13,841.72 cw(c2893.53,838.32) 2896.93,841.72 2907.14,831.51 cw(c2903.74,828.11) 2907.14,824.71 2876.76,794.33 ccw(c2880.16,790.93) 2876.76,787.53 2886.96,777.32 ccw(c2890.36,780.72) 2893.76,777.32 2924.14,807.71 cw(c2927.55,804.3) 2930.95,807.71 2941.15,797.5 cw(c2937.75,794.1) 2941.15,790.7 2910.77,760.32 ccw(c2914.17,756.92) 2910.77,753.51 2920.97,743.31 ccw(c2924.37,746.71) 2927.77,743.31 2958.16,773.69 cw(c2961.56,770.29) 2964.96,773.69 2975.16,763.49 cw(c2971.76,760.09) 2975.16,756.69 2944.78,726.31 ccw(c2948.18,722.9) 2944.78,719.5 2954.98,709.3 ccw(c2958.38,712.7) 2961.79,709.3 2992.17,739.68 cw(c2995.57,736.28) 2998.97,739.68 3009.17,729.48 cw(c3005.77,726.08) 3009.17,722.68 2978.79,692.29 ccw(c2982.19,688.89) 2978.79,685.49 2988.99,675.29 ccw(c2992.4,678.69) 2995.8,675.29 3026.18,705.67 cw(c3029.58,702.27) 3032.98,705.67 3043.19,695.47 cw(c3039.78,692.07) 3043.19,688.66 3040.9,686.38 ccw(c3044.3,682.98) 3040.9,679.57 3045.81,674.66 3047.24,673.23 3050.2,670.28 3051.63,668.84 ccw(c3055.03,672.24) 3058.43,668.84 3065.43,675.84 cw(c3068.83,672.44) 3072.23,675.84 3082.43,665.64 cw(c3079.03,662.23) 3082.43,658.83 3058.94,635.34 ccw(c3062.34,631.94) 3058.94,628.53 3069.14,618.33 ccw(c3072.54,621.73) 3075.94,618.33 3099.44,641.83 cw(c3102.84,638.43) 3106.24,641.83 3116.45,631.62 cw(c3113.04,628.22) 3116.45,624.82 3092.95,601.32 ccw(c3096.35,597.92) 3092.95,594.52 3103.15,584.32 ccw(c3106.55,587.72) 3109.95,584.32 3133.45,607.82 cw(c3136.85,604.41) 3140.25,607.82 3150.46,597.61 cw(c3147.06,594.21) 3150.46,590.81 3126.96,567.31 ccw(c3130.36,563.91) 3126.96,560.51 3137.16,550.31 ccw(c3140.56,553.71) 3143.97,550.31 3167.46,573.8 cw(c3170.86,570.4) 3174.27,573.8 3184.47,563.6 cw(c3181.07,560.2) 3184.47,556.8 3160.97,533.3 ccw(c3164.37,529.9) 3160.97,526.5 3171.18,516.29 ccw(c3174.58,519.7) 3177.98,516.3 3201.47,539.79 cw(c3204.88,536.39) 3208.28,539.79 3218.48,529.59 cw(c3215.08,526.19) 3218.48,522.79 3194.98,499.29 ccw(c3198.38,495.89) 3194.98,492.49 3205.19,482.28 ccw(c3208.59,485.68) 3211.99,482.28 3221.69,491.98 cw(c3225.09,488.58) 3228.49,491.98 3246.6,473.87 3248.03,472.44 3252,468.48 3252,370.21 v1(3261.37,360.84)
SZG_PORTE_S4: J6.19 MC3.149 | length 4985.3
  L1-TOP w4.55: MC3.149@2476.77,3730.32 2477.07,3730.01 2525.69,3730.01 2531.9,3736.22 v1(2535.43,3736.22) ; J6.19@3281.05,83.86 3281,83.91 3281,153.13 3287.11,159.24 v1(3287.11,162.52)
  L8-SIG w4.05: v1(2535.43,3736.22) 2594.78,3736.22 2626,3705 2626,3689 2652.5,3662.5 2674.5,3662.5 2745,3592 2831.05,3592 2877.95,3545.1 2877.95,3492.13 2926.24,3443.84 2927.67,3442.41 2944.67,3425.41 cw(c2941.27,3422) 2944.67,3418.6 2943.94,3417.87 ccw(c2947.34,3414.46) 2943.94,3411.06 2954.14,3400.86 ccw(c2957.54,3404.26) 2960.94,3400.86 2961.68,3401.6 cw(c2965.08,3398.2) 2968.48,3401.6 2978.23,3391.85 2979.66,3390.42 3035.25,3334.83 3035.25,1848.94 2859,1672.69 2859,936.28 2866.14,929.13 2867.57,927.7 ccw(c2870.98,931.1) 2874.38,927.7 2881.78,935.11 cw(c2885.18,931.7) 2888.58,935.11 2898.79,924.9 cw(c2895.38,921.5) 2898.79,918.1 2880.61,899.92 ccw(c2884.01,896.52) 2880.61,893.12 2890.81,882.92 ccw(c2894.22,886.32) 2897.62,882.92 2915.79,901.09 cw(c2919.19,897.69) 2922.59,901.09 2932.8,890.89 cw(c2929.4,887.49) 2932.8,884.09 2914.62,865.91 ccw(c2918.02,862.51) 2914.62,859.11 2924.83,848.91 ccw(c2928.23,852.31) 2931.63,848.91 2949.8,867.08 cw(c2953.2,863.68) 2956.61,867.08 2966.81,856.88 cw(c2963.41,853.48) 2966.81,850.08 2948.63,831.9 ccw(c2952.04,828.5) 2948.63,825.1 2958.84,814.89 ccw(c2962.24,818.3) 2965.64,814.89 2983.82,833.07 cw(c2987.22,829.67) 2990.62,833.07 3000.82,822.87 cw(c2997.42,819.47) 3000.82,816.06 2982.65,797.89 ccw(c2986.05,794.49) 2982.65,791.09 2992.85,780.88 ccw(c2996.25,784.28) 2999.65,780.88 3017.83,799.06 cw(c3021.23,795.66) 3024.63,799.06 3034.83,788.85 cw(c3031.43,785.45) 3034.83,782.05 3016.66,763.88 ccw(c3020.06,760.48) 3016.66,757.07 3026.86,746.87 ccw(c3030.26,750.27) 3033.66,746.87 3051.84,765.05 cw(c3055.24,761.65) 3058.64,765.05 3068.85,754.84 cw(c3065.44,751.44) 3068.85,748.04 3050.67,729.87 ccw(c3054.07,726.46) 3050.67,723.06 3060.87,712.86 ccw(c3064.27,716.26) 3067.68,712.86 3085.85,731.03 cw(c3089.25,727.63) 3092.65,731.03 3102.86,720.83 cw(c3099.46,717.43) 3102.86,714.03 3084.68,695.85 ccw(c3088.08,692.45) 3084.68,689.05 3094.89,678.85 ccw(c3098.29,682.25) 3101.69,678.85 3119.86,697.02 cw(c3123.26,693.62) 3126.67,697.02 3136.87,686.82 cw(c3133.47,683.42) 3136.87,680.02 3118.69,661.84 ccw(c3122.09,658.44) 3118.69,655.04 3128.9,644.84 ccw(c3132.3,648.24) 3135.7,644.84 3153.87,663.01 cw(c3157.28,659.61) 3160.68,663.01 3170.88,652.81 cw(c3167.48,649.41) 3170.88,646.01 3152.71,627.83 ccw(c3156.11,624.43) 3152.71,621.03 3162.91,610.82 ccw(c3166.31,614.22) 3169.71,610.82 3187.89,629 cw(c3191.29,625.6) 3194.69,629 3204.89,618.8 cw(c3201.49,615.39) 3204.89,611.99 3186.72,593.82 ccw(c3190.12,590.42) 3186.72,587.02 3196.92,576.81 ccw(c3200.32,580.21) 3203.72,576.81 3221.9,594.99 cw(c3225.3,591.59) 3228.7,594.99 3238.9,584.78 cw(c3235.5,581.38) 3238.9,577.98 3220.73,559.81 ccw(c3224.13,556.4) 3220.73,553 3230.93,542.8 ccw(c3234.33,546.2) 3237.73,542.8 3241.7,546.77 cw(c3245.11,543.37) 3248.51,546.77 3261.79,533.49 3263.22,532.05 3285.23,510.04 3285.23,327.88 3263,305.65 3263,235 3280.25,217.75 3280.25,171.25 3287.11,164.39 v1(3287.11,162.52)
SZG_PORTE_S5: J6.20 MC3.138 | length 4902.2
  L8-SIG w4.05: v1(2754.08,3612.2) 2838.41,3612.2 2916.25,3534.36 2917.68,3532.93 2934.69,3515.92 cw(c2931.29,3512.52) 2934.69,3509.12 2919.3,3493.73 ccw(c2922.7,3490.33) 2919.3,3486.93 2929.5,3476.73 ccw(c2932.91,3480.13) 2936.31,3476.73 2951.75,3492.17 cw(c2955.15,3488.77) 2958.55,3492.17 2968.76,3481.97 cw(c2965.36,3478.57) 2968.76,3475.17 2955.96,3462.37 ccw(c2959.36,3458.97) 2955.96,3455.57 2966.17,3445.37 ccw(c2969.57,3448.77) 2972.97,3445.36 2985.71,3458.1 cw(c2989.11,3454.7) 2992.51,3458.1 3008.86,3441.75 3010.29,3440.32 3054.47,3396.14 3054.47,1833.99 2873,1652.53 2873,1008.89 2874.49,1007.4 2875.92,1005.97 ccw(c2879.33,1009.37) 2882.73,1005.97 2896.59,1019.83 cw(c2899.99,1016.43) 2903.4,1019.83 2913.6,1009.63 cw(c2910.2,1006.23) 2913.6,1002.83 2887.69,976.92 ccw(c2891.09,973.51) 2887.69,970.11 2897.89,959.91 ccw(c2901.29,963.31) 2904.69,959.91 2930.61,985.82 cw(c2934.01,982.42) 2937.41,985.82 2947.61,975.62 cw(c2944.21,972.22) 2947.61,968.81 2921.7,942.9 ccw(c2925.1,939.5) 2921.7,936.1 2931.9,925.9 ccw(c2935.3,929.3) 2938.71,925.9 2964.62,951.81 cw(c2968.02,948.41) 2971.42,951.81 2981.62,941.61 cw(c2978.22,938.2) 2981.62,934.8 2955.71,908.89 ccw(c2959.11,905.49) 2955.71,902.09 2965.92,891.89 ccw(c2969.32,895.29) 2972.72,891.89 2998.63,917.8 cw(c3002.03,914.4) 3005.43,917.8 3015.64,907.59 cw(c3012.23,904.19) 3015.64,900.79 2989.72,874.88 ccw(c2993.12,871.48) 2989.72,868.08 2999.93,857.87 ccw(c3003.33,861.28) 3006.73,857.87 3032.64,883.79 cw(c3036.04,880.38) 3039.44,883.79 3049.65,873.58 cw(c3046.25,870.18) 3049.65,866.78 3023.74,840.87 ccw(c3027.14,837.47) 3023.74,834.07 3033.94,823.86 ccw(c3037.34,827.26) 3040.74,823.86 3066.65,849.77 cw(c3070.05,846.37) 3073.46,849.77 3083.66,839.57 cw(c3080.26,836.17) 3083.66,832.77 3057.75,806.86 ccw(c3061.15,803.46) 3057.75,800.05 3067.95,789.85 ccw(c3071.35,793.25) 3074.75,789.85 3100.66,815.76 cw(c3104.07,812.36) 3107.47,815.76 3117.67,805.56 cw(c3114.27,802.16) 3117.67,798.76 3091.76,772.84 ccw(c3095.16,769.44) 3091.76,766.04 3101.96,755.84 ccw(c3105.36,759.24) 3108.77,755.84 3134.68,781.75 cw(c3138.08,778.35) 3141.48,781.75 3151.68,771.55 cw(c3148.28,768.14) 3151.68,764.74 3125.77,738.83 ccw(c3129.17,735.43) 3125.77,732.03 3135.97,721.83 ccw(c3139.38,725.23) 3142.78,721.83 3168.69,747.74 cw(c3172.09,744.34) 3175.49,747.74 3185.69,737.53 cw(c3182.29,734.13) 3185.69,730.73 3159.78,704.82 ccw(c3163.18,701.42) 3159.78,698.02 3169.99,687.81 ccw(c3173.39,691.22) 3176.79,687.81 3202.7,713.73 cw(c3206.1,710.33) 3209.5,713.73 3219.71,703.52 cw(c3216.3,700.12) 3219.71,696.72 3193.79,670.81 ccw(c3197.2,667.41) 3193.79,664.01 3204,653.8 ccw(c3207.4,657.2) 3210.8,653.8 3236.71,679.71 cw(c3240.11,676.31) 3243.51,679.71 3253.72,669.51 cw(c3250.32,666.11) 3253.72,662.71 3227.81,636.8 ccw(c3231.21,633.4) 3227.81,629.99 3238.01,619.79 ccw(c3241.41,623.19) 3244.81,619.79 3270.72,645.7 cw(c3274.12,642.3) 3277.53,645.7 3287.73,635.5 cw(c3284.33,632.1) 3287.73,628.7 3261.82,602.79 ccw(c3265.22,599.38) 3261.82,595.98 3272.02,585.78 ccw(c3275.42,589.18) 3278.82,585.78 3284.07,591.02 cw(c3287.47,587.62) 3290.87,591.02 3297.78,584.11 3299.21,582.68 3307.67,574.22 3307.67,388.16 3299.21,379.7 3299.21,318.9 3281.05,300.74 v1(3281.05,258.84)
SZG_PORTE_S6: J6.21 MC3.140 | length 4935.8
  L1-TOP w4.55: MC3.140@2720.08,3631.89 2760.59,3631.89 2774.37,3618.11 2854.33,3618.11 2877.95,3594.49 v1(2917.32,3594.49)
  L8-SIG w4.05: v1(2917.32,3594.49) 2950.65,3561.17 2952.08,3559.73 ccw(c2955.48,3563.13) 2958.88,3559.73 cw(c2962.28,3556.33) 2965.68,3559.73 2975.89,3549.53 cw(c2972.49,3546.13) 2975.89,3542.73 ccw(c2979.29,3539.33) 2975.89,3535.92 2988.55,3523.26 2989.98,3521.83 3096.44,3415.37 3096.44,1807.6 2965.5,1676.66 2965.5,1577.5 2956,1568 2956,1466 2941.37,1451.37 2941.37,1113.74 2952.76,1102.36 2954.19,1100.93 ccw(c2957.59,1104.33) 2960.99,1100.93 2982.98,1122.92 cw(c2986.38,1119.52) 2989.78,1122.92 2999.99,1112.72 cw(c2996.58,1109.32) 2999.99,1105.91 2973.76,1079.69 ccw(c2977.16,1076.28) 2973.76,1072.88 2983.96,1062.68 ccw(c2987.36,1066.08) 2990.76,1062.68 3016.99,1088.91 cw(c3020.39,1085.51) 3023.79,1088.91 3034,1078.7 cw(c3030.6,1075.3) 3034,1071.9 3007.77,1045.67 ccw(c3011.17,1042.27) 3007.77,1038.87 3017.97,1028.67 ccw(c3021.37,1032.07) 3024.78,1028.67 3051,1054.9 cw(c3054.4,1051.49) 3057.81,1054.9 3068.01,1044.69 cw(c3064.61,1041.29) 3068.01,1037.89 3041.78,1011.66 ccw(c3045.18,1008.26) 3041.78,1004.86 3051.98,994.66 ccw(c3055.39,998.06) 3058.79,994.66 3085.02,1020.88 cw(c3088.42,1017.48) 3091.82,1020.88 3102.02,1010.68 cw(c3098.62,1007.28) 3102.02,1003.88 3075.79,977.65 ccw(c3079.19,974.25) 3075.79,970.85 3086,960.64 ccw(c3089.4,964.05) 3092.8,960.64 3119.03,986.87 cw(c3122.43,983.47) 3125.83,986.87 3136.03,976.67 cw(c3132.63,973.27) 3136.03,969.87 3109.8,943.64 ccw(c3113.21,940.24) 3109.8,936.84 3120.01,926.63 ccw(c3123.41,930.03) 3126.81,926.63 3153.04,952.86 cw(c3156.44,949.46) 3159.84,952.86 3170.05,942.66 cw(c3166.64,939.26) 3170.05,935.85 3143.82,909.63 ccw(c3147.22,906.23) 3143.82,902.82 3154.02,892.62 ccw(c3157.42,896.02) 3160.82,892.62 3187.05,918.85 cw(c3190.45,915.45) 3193.85,918.85 3204.06,908.65 cw(c3200.66,905.24) 3204.06,901.84 3177.83,875.61 ccw(c3181.23,872.21) 3177.83,868.81 3188.03,858.61 ccw(c3191.43,862.01) 3194.83,858.61 3221.06,884.84 cw(c3224.46,881.44) 3227.87,884.84 3238.07,874.63 cw(c3234.67,871.23) 3238.07,867.83 3211.84,841.6 ccw(c3215.24,838.2) 3211.84,834.8 3222.04,824.6 ccw(c3225.45,828) 3228.85,824.6 3255.07,850.83 cw(c3258.48,847.42) 3261.88,850.82 3272.08,840.62 cw(c3268.68,837.22) 3272.08,833.82 3245.85,807.59 ccw(c3249.25,804.19) 3245.85,800.79 3256.06,790.58 ccw(c3259.46,793.99) 3262.86,790.58 3289.09,816.81 cw(c3292.49,813.41) 3295.89,816.81 3306.09,806.61 cw(c3302.69,803.21) 3306.09,799.81 3279.86,773.58 ccw(c3283.27,770.18) 3279.86,766.78 3290.07,756.57 ccw(c3293.47,759.97) 3296.87,756.57 3323.1,782.8 cw(c3326.5,779.4) 3329.9,782.8 3340.1,772.6 cw(c3336.7,769.2) 3340.1,765.8 3318.11,743.81 ccw(c3321.52,740.4) 3318.11,737 3352.9,702.22 3354.33,700.79 3359.24,695.88 3359.24,323.8 3320.42,284.99 v1(3320.42,134.86)
SZG_PORTE_S7: J6.22 MC3.142 | length 4900.4
  L8-SIG w4.05: v1(2754.08,3651.58) 2824.8,3651.58 3076.44,3399.94 3076.44,1816.6 2947,1687.16 2947,1587 2915.53,1555.53 2915.53,1484.25 2915.53,1458.18 cw(c2910.72,1458.18) 2910.72,1453.37 2895.34,1453.37 ccw(c2895.34,1448.56) 2890.53,1448.56 2890.53,1434.13 ccw(c2895.34,1434.13) 2895.34,1429.32 2915.23,1429.32 cw(c2915.23,1424.51) 2920.04,1424.51 2920.04,1410.08 cw(c2915.23,1410.08) 2915.23,1405.27 2895.34,1405.27 ccw(c2895.34,1400.46) 2890.53,1400.46 2890.53,1386.03 ccw(c2895.34,1386.03) 2895.34,1381.22 2915.23,1381.22 cw(c2915.23,1376.41) 2920.04,1376.41 2920.04,1361.98 cw(c2915.23,1361.98) 2915.23,1357.17 2895.34,1357.17 ccw(c2895.34,1352.36) 2890.53,1352.36 2890.53,1337.93 ccw(c2895.34,1337.93) 2895.34,1333.12 2915.23,1333.12 cw(c2915.23,1328.31) 2920.04,1328.31 2920.04,1313.88 cw(c2915.23,1313.88) 2915.23,1309.07 2895.34,1309.07 ccw(c2895.34,1304.26) 2890.53,1304.26 2890.53,1289.83 ccw(c2895.34,1289.83) 2895.34,1285.02 2915.23,1285.02 cw(c2915.23,1280.21) 2920.04,1280.21 2920.04,1265.78 cw(c2915.23,1265.78) 2915.23,1260.97 2895.34,1260.97 ccw(c2895.34,1256.16) 2890.53,1256.16 2890.53,1241.73 ccw(c2895.34,1241.73) 2895.34,1236.92 2915.23,1236.92 cw(c2915.23,1232.11) 2920.04,1232.11 2920.04,1217.68 cw(c2915.23,1217.68) 2915.23,1212.87 2895.34,1212.87 ccw(c2895.34,1208.06) 2890.53,1208.06 2890.53,1193.63 ccw(c2895.34,1193.63) 2895.34,1188.82 2915.23,1188.82 cw(c2915.23,1184.01) 2920.04,1184.01 2920.04,1169.58 cw(c2915.23,1169.58) 2915.23,1164.77 2907.8,1164.77 ccw(c2907.8,1159.96) 2902.99,1159.96 2902.99,1145.53 ccw(c2907.8,1145.53) 2907.8,1140.72 2910.72,1140.72 cw(c2910.72,1135.91) 2915.53,1135.91 2915.53,1090.9 2915.53,1052.97 2921.26,1047.24 2922.69,1045.81 ccw(c2926.09,1049.21) 2929.49,1045.81 2947.21,1063.52 cw(c2950.61,1060.12) 2954.01,1063.52 2964.21,1053.32 cw(c2960.81,1049.92) 2964.21,1046.52 2941.94,1024.24 ccw(c2945.34,1020.84) 2941.94,1017.44 2952.14,1007.24 ccw(c2955.54,1010.64) 2958.94,1007.24 2981.22,1029.51 cw(c2984.62,1026.11) 2988.02,1029.51 2998.22,1019.31 cw(c2994.82,1015.91) 2998.22,1012.51 2975.95,990.23 ccw(c2979.35,986.83) 2975.95,983.43 2986.15,973.22 ccw(c2989.55,976.62) 2992.95,973.22 3015.23,995.5 cw(c3018.63,992.1) 3022.03,995.5 3032.24,985.3 cw(c3028.83,981.89) 3032.24,978.49 3009.96,956.22 ccw(c3013.36,952.82) 3009.96,949.42 3020.16,939.21 ccw(c3023.56,942.61) 3026.97,939.21 3049.24,961.49 cw(c3052.64,958.09) 3056.04,961.49 3066.25,951.28 cw(c3062.85,947.88) 3066.25,944.48 3043.97,922.21 ccw(c3047.37,918.8) 3043.97,915.4 3054.17,905.2 ccw(c3057.58,908.6) 3060.98,905.2 3083.25,927.48 cw(c3086.65,924.08) 3090.06,927.48 3100.26,917.27 cw(c3096.86,913.87) 3100.26,910.47 3077.98,888.19 ccw(c3081.38,884.79) 3077.98,881.39 3088.19,871.19 ccw(c3091.59,874.59) 3094.99,871.19 3117.27,893.46 cw(c3120.67,890.06) 3124.07,893.46 3134.27,883.26 cw(c3130.87,879.86) 3134.27,876.46 3111.99,854.18 ccw(c3115.4,850.78) 3111.99,847.38 3122.2,837.18 ccw(c3125.6,840.58) 3129,837.18 3151.28,859.45 ; 3151.28,859.45 cw(c3154.68,856.05) 3158.08,859.45 3168.28,849.25 cw(c3164.88,845.85) 3168.28,842.45 3146.01,820.17 ccw(c3149.41,816.77) 3146.01,813.37 3156.21,803.16 ccw(c3159.61,806.57) 3163.01,803.16 3185.29,825.44 cw(c3188.69,822.04) 3192.09,825.44 3202.29,815.24 cw(c3198.89,811.84) 3202.29,808.43 3180.02,786.16 ccw(c3183.42,782.76) 3180.02,779.36 3190.22,769.15 ccw(c3193.62,772.55) 3197.02,769.15 3219.3,791.43 cw(c3222.7,788.03) 3226.1,791.43 3236.31,781.23 cw(c3232.91,777.82) 3236.31,774.42 3214.03,752.15 ccw(c3217.43,748.75) 3214.03,745.34 3224.23,735.14 ccw(c3227.64,738.54) 3231.04,735.14 3253.31,757.42 cw(c3256.71,754.02) 3260.11,757.42 3270.32,747.21 cw(c3266.92,743.81) 3270.32,740.41 3248.04,718.13 ccw(c3251.44,714.73) 3248.04,711.33 3258.25,701.13 ccw(c3261.65,704.53) 3265.05,701.13 3287.32,723.41 cw(c3290.73,720) 3294.13,723.41 3304.33,713.2 cw(c3300.93,709.8) 3304.33,706.4 3282.05,684.12 ccw(c3285.46,680.72) 3282.05,677.32 3292.26,667.12 ccw(c3295.66,670.52) 3299.06,667.12 3321.34,689.39 cw(c3324.74,685.99) 3328.14,689.39 3338.34,679.19 cw(c3334.94,675.79) 3338.34,672.39 3320.63,654.68 ccw(c3324.03,651.27) 3320.63,647.87 3325.27,643.24 3325.27,632.35 3325.27,369.46 3320.42,364.62 v1(3320.42,360.84)
SZG_PORTE_S8: J6.23 MC3.144 | length 4933.6
  L1-TOP w4.55: MC3.144@2720.08,3671.26 2760.04,3671.26 2777.76,3653.54 2879.41,3653.54 2903.04,3629.92 v1(2929.13,3629.92)
  L8-SIG w4.05: v1(2929.13,3629.92) 3116.44,3442.61 3116.44,1783.71 3031,1698.26 3031,1613 2993,1575 2993,1473 2963.51,1443.51 2963.51,1186.1 2968.5,1181.1 2969.94,1179.67 ccw(c2973.34,1183.07) 2976.74,1179.67 2997.15,1200.08 cw(c3000.55,1196.68) 3003.95,1200.08 3014.15,1189.88 cw(c3010.75,1186.47) 3014.15,1183.07 2988.79,1157.71 ccw(c2992.19,1154.31) 2988.79,1150.91 2999,1140.71 ccw(c3002.4,1144.11) 3005.8,1140.71 3031.16,1166.07 cw(c3034.56,1162.67) 3037.96,1166.07 3048.17,1155.86 cw(c3044.76,1152.46) 3048.17,1149.06 3022.8,1123.7 ccw(c3026.21,1120.3) 3022.8,1116.9 3033.01,1106.7 ccw(c3036.41,1110.1) 3039.81,1106.7 3065.17,1132.06 cw(c3068.57,1128.65) 3071.97,1132.06 3082.18,1121.85 cw(c3078.78,1118.45) 3082.18,1115.05 3056.82,1089.69 ccw(c3060.22,1086.29) 3056.82,1082.89 3067.02,1072.68 ccw(c3070.42,1076.08) 3073.82,1072.68 3099.18,1098.04 cw(c3102.58,1094.64) 3105.99,1098.04 3116.19,1087.84 cw(c3112.79,1084.44) 3116.19,1081.04 3090.83,1055.68 ccw(c3094.23,1052.28) 3090.83,1048.88 3101.03,1038.67 ccw(c3104.43,1042.07) 3107.83,1038.67 3133.19,1064.03 cw(c3136.6,1060.63) 3140,1064.03 3150.2,1053.83 cw(c3146.8,1050.43) 3150.2,1047.03 3124.84,1021.67 ccw(c3128.24,1018.26) 3124.84,1014.86 3135.04,1004.66 ccw(c3138.45,1008.06) 3141.85,1004.66 3167.21,1030.02 cw(c3170.61,1026.62) 3174.01,1030.02 3184.21,1019.82 cw(c3180.81,1016.42) 3184.21,1013.01 3158.85,987.65 ccw(c3162.25,984.25) 3158.85,980.85 3169.06,970.65 ccw(c3172.46,974.05) 3175.86,970.65 3201.22,996.01 cw(c3204.62,992.61) 3208.02,996.01 3218.22,985.8 cw(c3214.82,982.4) 3218.22,979 3192.86,953.64 ccw(c3196.27,950.24) 3192.86,946.84 3203.07,936.64 ccw(c3206.47,940.04) 3209.87,936.64 3235.23,962 cw(c3238.63,958.6) 3242.03,962 3252.24,951.79 cw(c3248.84,948.39) 3252.24,944.99 3226.88,919.63 ccw(c3230.28,916.23) 3226.88,912.83 3237.08,902.62 ccw(c3240.48,906.03) 3243.88,902.62 3269.24,927.98 cw(c3272.64,924.58) 3276.04,927.98 3286.25,917.78 cw(c3282.85,914.38) 3286.25,910.98 3260.89,885.62 ccw(c3264.29,882.22) 3260.89,878.82 3271.09,868.61 ccw(c3274.49,872.01) 3277.89,868.61 3290.12,880.84 cw(c3293.53,877.44) 3296.93,880.84 3307.13,870.64 cw(c3303.73,867.24) 3307.13,863.84 3299.85,856.56 ccw(c3303.25,853.16) 3299.85,849.76 3315.5,834.11 3316.93,832.68 3377.33,772.28 3377.33,314.37 3332.08,269.11 3332.08,189.38 3340.11,181.35 v1(3340.11,32.86)
SZG_PORTE_S9: J6.24 MC3.146 | length 4953.2
  L1-TOP w4.55: J6.24@3340.11,309.84 3340.11,264.11 v1(3352.46,251.76)
  L8-SIG w4.05: v1(2754.08,3690.95) 2899.05,3690.95 3138.87,3451.13 3138.87,1781.47 3054.5,1697.1 3054.5,1600.5 3012,1558 3012,1462 2984.04,1434.04 2984.04,1244.31 3395.42,832.93 3395.42,819.04 3395.42,817.02 ccw(c3400.23,817.02) 3400.23,812.21 3438.24,812.21 cw(c3438.24,807.4) 3443.05,807.4 3443.05,792.97 cw(c3438.24,792.97) 3438.24,788.16 3398.02,788.16 ccw(c3398.02,783.35) 3393.21,783.35 3393.21,768.92 ccw(c3398.02,768.92) 3398.02,764.11 3438.24,764.11 cw(c3438.24,759.3) 3443.05,759.3 3443.05,744.87 cw(c3438.24,744.87) 3438.24,740.06 3398.02,740.06 ccw(c3398.02,735.25) 3393.21,735.25 3393.21,720.82 ccw(c3398.02,720.82) 3398.02,716.01 3438.24,716.01 cw(c3438.24,711.2) 3443.05,711.2 3443.05,696.77 cw(c3438.24,696.77) 3438.24,691.96 3398.02,691.96 ccw(c3398.02,687.15) 3393.21,687.15 3393.21,672.72 ccw(c3398.02,672.72) 3398.02,667.91 3438.24,667.91 cw(c3438.24,663.1) 3443.05,663.1 3443.05,648.67 cw(c3438.24,648.67) 3438.24,643.86 3398.02,643.86 ccw(c3398.02,639.05) 3393.21,639.05 3393.21,624.62 ccw(c3398.02,624.62) 3398.02,619.81 3438.24,619.81 cw(c3438.24,615) 3443.05,615 3443.05,600.57 cw(c3438.24,600.57) 3438.24,595.76 3398.02,595.76 ccw(c3398.02,590.95) 3393.21,590.95 3393.21,576.52 ccw(c3398.02,576.52) 3398.02,571.71 3438.24,571.71 cw(c3438.24,566.9) 3443.05,566.9 3443.05,552.47 cw(c3438.24,552.47) 3438.24,547.66 3398.02,547.66 ccw(c3398.02,542.85) 3393.21,542.85 3393.21,528.42 ccw(c3398.02,528.42) 3398.02,523.61 3438.24,523.61 cw(c3438.24,518.8) 3443.05,518.8 3443.05,504.37 cw(c3438.24,504.37) 3438.24,499.56 3398.02,499.56 ccw(c3398.02,494.75) 3393.21,494.75 3393.21,480.32 ccw(c3398.02,480.32) 3398.02,475.51 3438.24,475.51 cw(c3438.24,470.7) 3443.05,470.7 3443.05,456.27 cw(c3438.24,456.27) 3438.24,451.46 3398.02,451.46 ccw(c3398.02,446.65) 3393.21,446.65 3393.21,432.22 ccw(c3398.02,432.22) 3398.02,427.41 3438.24,427.41 cw(c3438.24,422.6) 3443.05,422.6 3443.05,408.17 cw(c3438.24,408.17) 3438.24,403.36 3398.02,403.36 ccw(c3398.02,398.55) 3393.21,398.55 3393.21,384.12 ccw(c3398.02,384.12) 3398.02,379.31 3438.24,379.31 cw(c3438.24,374.5) 3443.05,374.5 3443.05,360.07 cw(c3438.24,360.07) 3438.24,355.26 3398.02,355.26 ccw(c3398.02,350.45) 3393.21,350.45 3393.21,336.02 ccw(c3398.02,336.02) 3398.02,331.21 3414.69,331.21 cw(c3414.69,326.4) 3419.5,326.4 3419.5,311.97 cw(c3414.69,311.97) 3414.69,307.16 3400.23,307.16 ccw(c3400.23,302.35) 3395.42,302.35 3395.42,295.42 3395.42,294.72 v1(3352.46,251.76)
SZG_PORTE_TX0N: J6.8 MC2.84 | length 2245.3
  L1-TOP w3.3: J6.8@3103.89,309.84 3103.89,270.48 3098.54,265.13 3098.54,254 3125.27,227.28 3572.28,227.28 3642,297 3642,555.73 4532.27,1446 4559.16,1446 4571.43,1433.73 4571.43,1422.48 4576.77,1417.13 MC2.84@4576.77,1394.09
SZG_PORTE_TX0P: J6.6 MC2.82 | length 2245.3
  L1-TOP w3.3: J6.6@3084.2,309.84 3084.2,270.91 3089.54,265.57 3089.54,250.27 3121.54,218.28 3576.01,218.28 3578.64,220.91 3651,293.27 3651,552 4536,1437 4555.43,1437 4562.43,1430 4562.43,1422.39 4557.09,1417.05 MC2.82@4557.09,1394.09
SZG_PORTE_TX1N: J6.12 MC2.80 | length 2028.1
  L1-TOP w3.3: J6.12@3162.94,309.84 3162.94,348.97 3157.6,354.32 3157.6,421.38 3944.88,1208.66 3962.52,1226.3 cw(c3965.82,1223.01) 3969.11,1226.3 3980.2,1215.22 ccw(c3983.5,1218.51) 3986.79,1215.22 3996.68,1225.1 ccw(c3993.38,1228.4) 3996.68,1231.69 3985.59,1242.78 cw(c3988.89,1246.07) 3985.59,1249.37 3995.48,1259.26 cw(c3998.77,1255.96) 4002.07,1259.26 4004.54,1256.78 ccw(c4007.84,1260.07) 4011.13,1256.78 4021.02,1266.66 ccw(c4017.72,1269.96) 4021.02,1273.25 4018.54,1275.73 cw(c4021.84,1279.03) 4018.54,1282.32 4031.5,1295.28 4059.3,1323.08 4091.27,1323.08 4108.89,1340.71 4108.89,1427.79 4122.05,1440.94 4338.58,1440.94 4362.2,1417.32 4362.2,1354.33 4346.46,1338.58 4327.33,1338.58 4315.52,1350.39 4315.52,1366.11 4320.87,1371.46 MC2.80@4320.87,1394.09
SZG_PORTE_TX1P: J6.10 MC2.78 | length 2028.1
  L1-TOP w3.3: J6.10@3143.26,309.84 3143.26,349.34 3148.6,354.68 3148.6,425.11 4055.57,1332.08 4087.54,1332.08 4099.89,1344.44 4099.89,1431.52 4118.32,1449.94 4342.31,1449.94 4371.2,1421.05 4371.2,1350.6 4350.18,1329.58 4323.61,1329.58 4306.52,1346.67 4306.52,1366.11 4301.18,1371.46 MC2.78@4301.18,1394.09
